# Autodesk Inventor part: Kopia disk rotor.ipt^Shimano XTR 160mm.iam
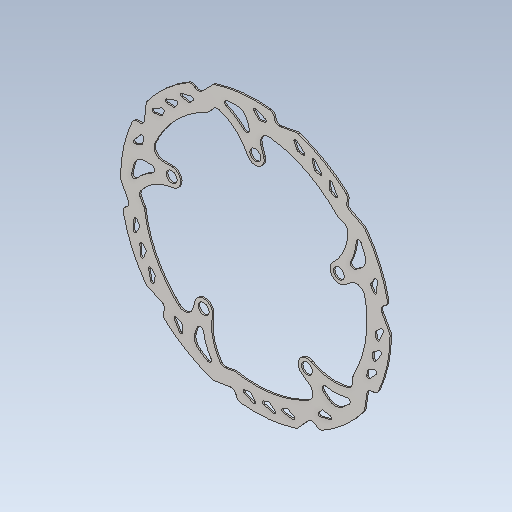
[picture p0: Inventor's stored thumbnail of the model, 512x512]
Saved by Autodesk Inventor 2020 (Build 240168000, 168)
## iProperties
Created: 2017-09
Part Number: Kopia disk rotor.ipt^Shimano XTR 160mm.iam
Material: Ogólny
Document SubType Name: Modeling
Designer: Tomasz
Density: 1 g/cm^3
Appearance: Domyślna
Sending System: SolidWorks 2017
Last Author: Tomasz
Last Saved: 2017-09-11
Author: Tomasz
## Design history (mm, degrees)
feature "disk rotor.ipt"
node "Bryła1"
